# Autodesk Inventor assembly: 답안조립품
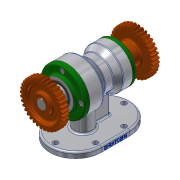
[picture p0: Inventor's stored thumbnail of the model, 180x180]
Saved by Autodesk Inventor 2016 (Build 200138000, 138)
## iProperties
Created: 2020-01
Part Number: 답안조립품
Document SubType Name: Assembly
Designer: woori
Author: woori
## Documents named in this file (13)
- C:\Users\woori\Desktop\700104V1013\답안조립품.iam
- C:\Users\woori\Desktop\700104V1013\본체.ipt
- C:\Users\woori\Desktop\700104V1013\볼트 M4.ipt
- C:\Users\woori\Desktop\700104V1013\스퍼기어.ipt
- C:\Users\woori\Desktop\700104V1013\앞커버.ipt
- C:\Users\woori\Desktop\700104V1013\오일 실 17 30 8.ipt
- C:\Users\woori\Desktop\700104V1013\오일 실 25 38 8.ipt
- C:\Users\woori\Desktop\700104V1013\축.ipt
- C:\Users\woori\Desktop\700104V1013\키 5 x 5 x 18.ipt
- C:\Users\woori\Desktop\700104V1013\뒤커버.ipt
- C:\Users\woori\Desktop\700104V1013\멈춤나사 M3.ipt
- C:\Users\woori\Desktop\700104V1013\베어링 6203.ipt
- C:\Users\woori\Desktop\700104V1013\베어링 6205.ipt
